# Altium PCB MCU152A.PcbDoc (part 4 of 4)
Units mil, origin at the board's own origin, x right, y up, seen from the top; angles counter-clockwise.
Board outline 2307.9 x 3007.9 mil, 4 copper layers (Top Signal, GND, PWR, Bottom Signal), stack 61.6 mil thick; 198 components, 136 nets, 740 pads, 401 vias.
Unrouted connection lines stored in the file: 147.
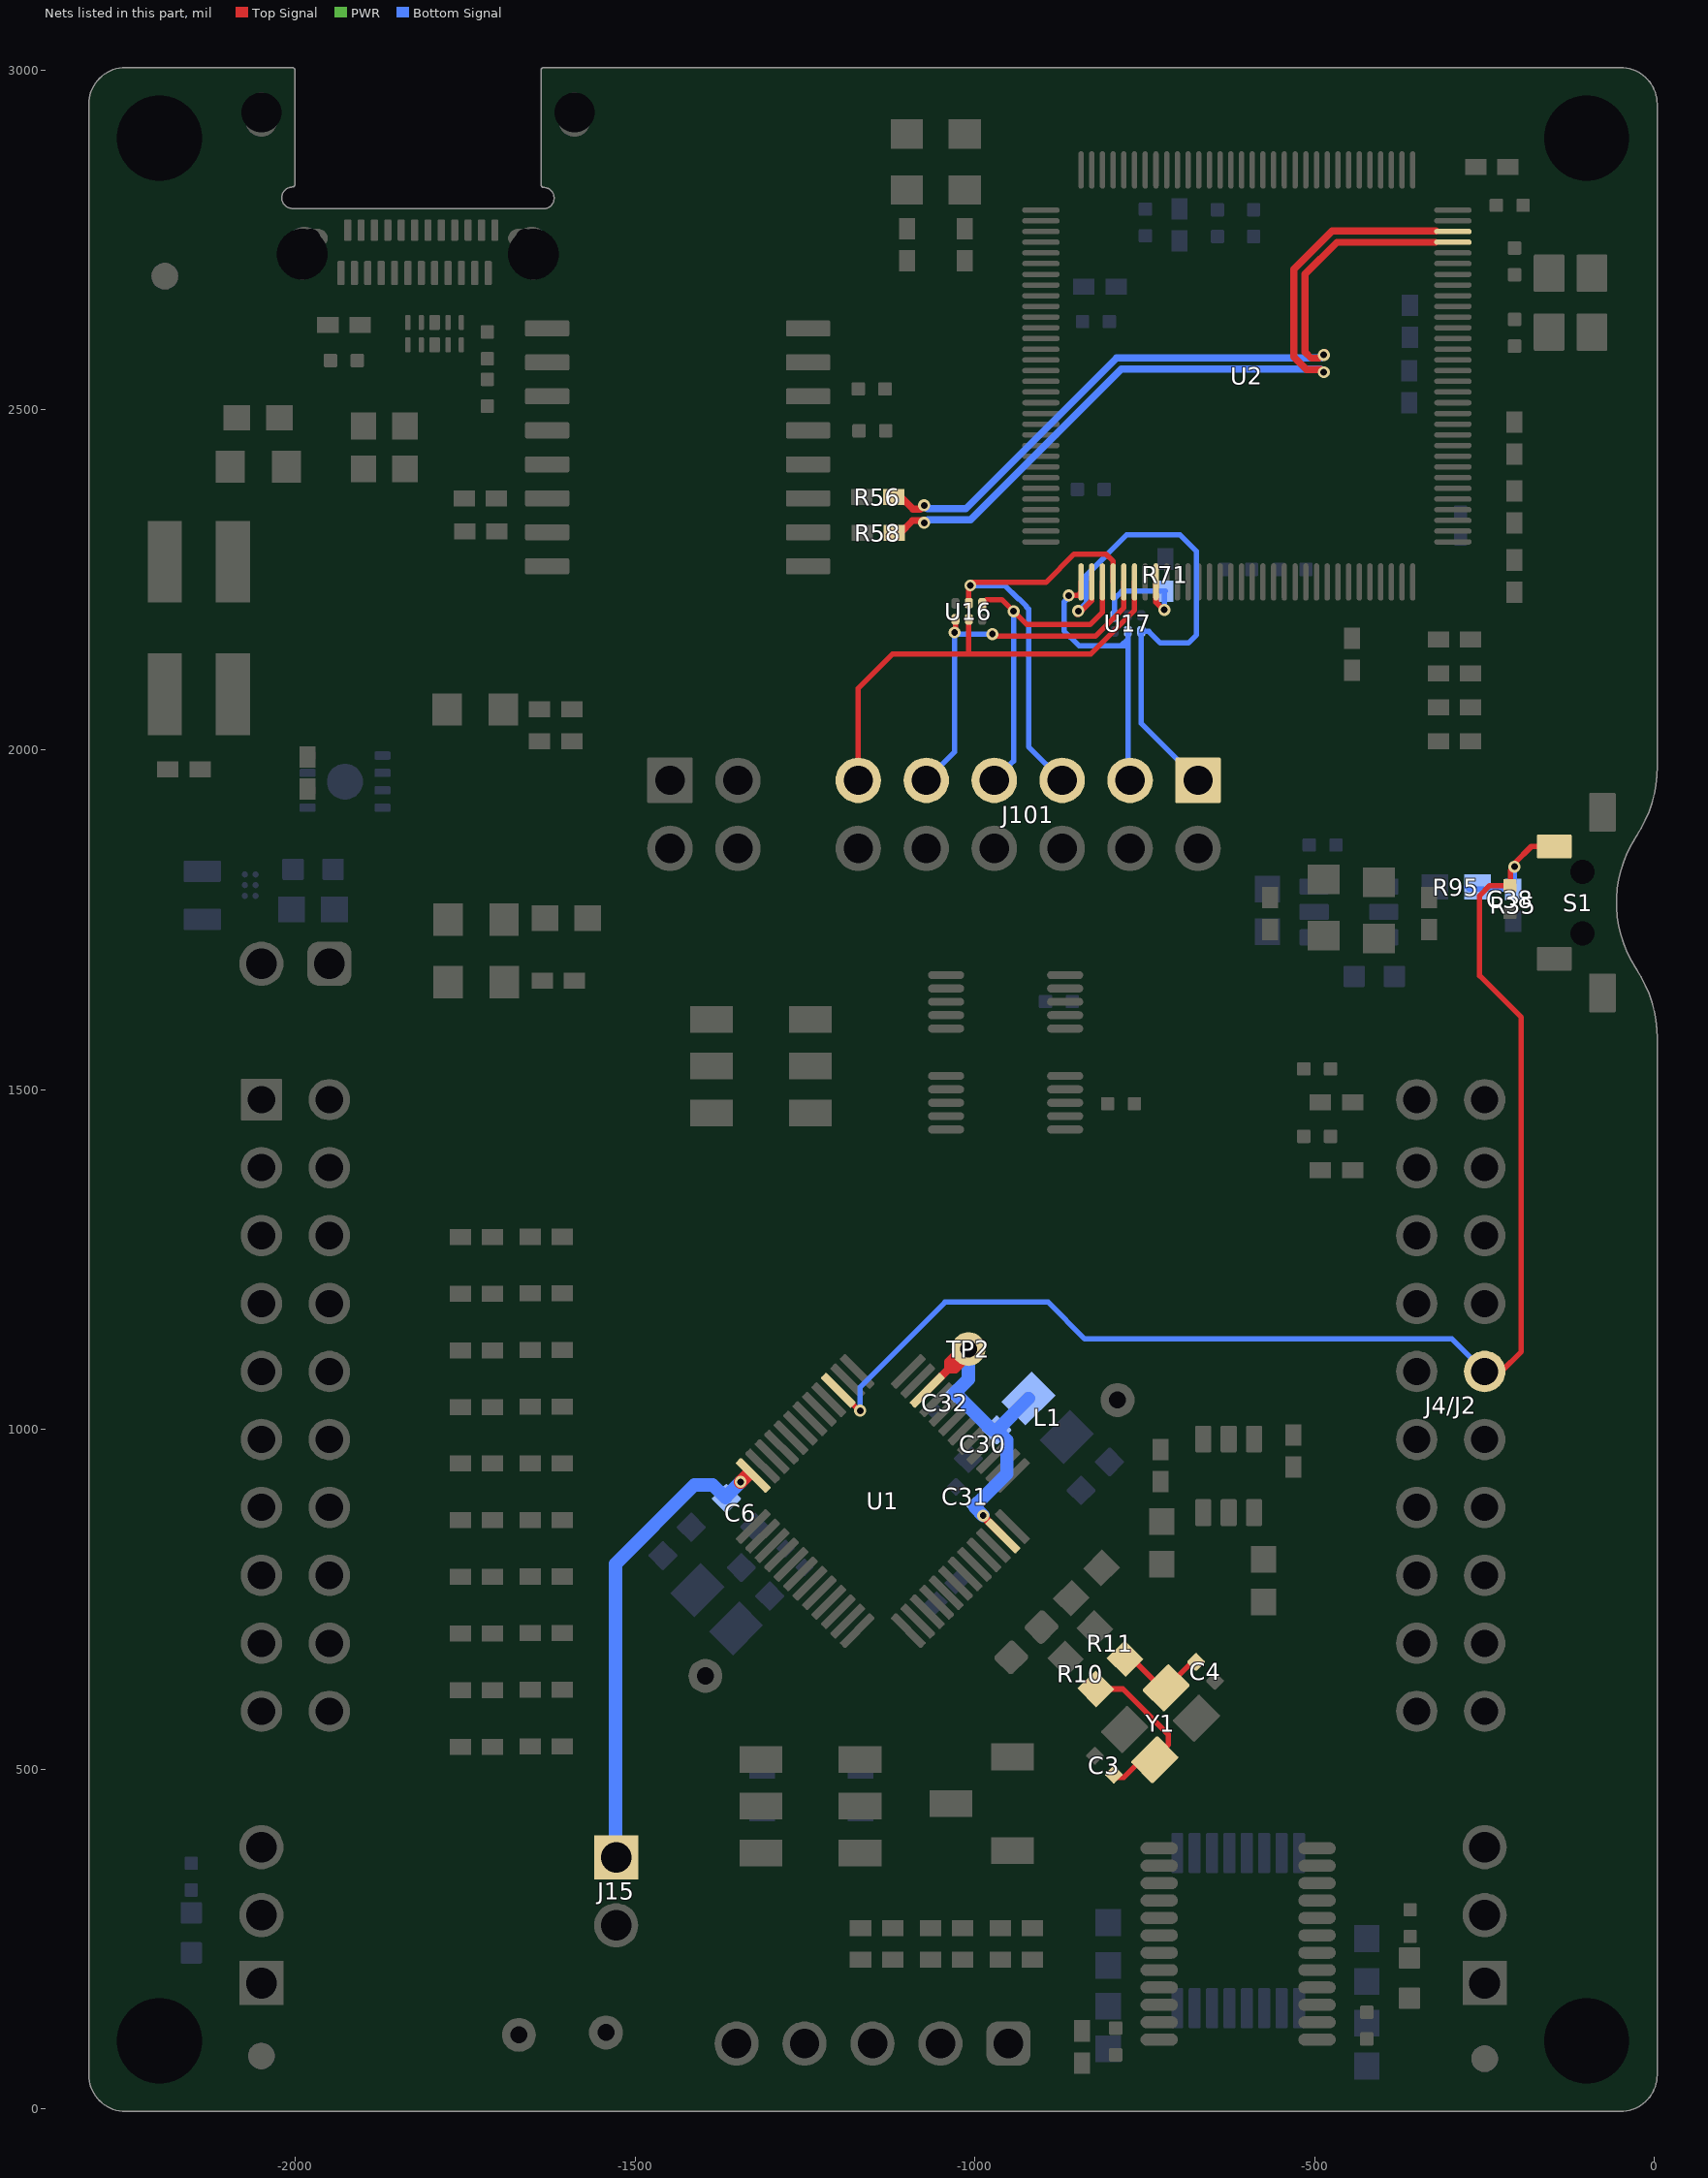
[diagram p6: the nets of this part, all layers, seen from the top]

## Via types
v1: diameter 17.72, hole 9.84, Top Signal to Bottom Signal, tented both sides, 368 vias
v2: diameter 27.56, hole 15.75, Top Signal to Bottom Signal, tented both sides, 21 vias
v3: diameter 19.68, hole 11.81, Top Signal to Bottom Signal, tented both sides, 6 vias
v4: diameter 19.68, hole 7.87, Top Signal to Bottom Signal, tented both sides, 4 vias
v5: diameter 15.75, hole 7.87, Top Signal to Bottom Signal, tented both sides, 2 vias

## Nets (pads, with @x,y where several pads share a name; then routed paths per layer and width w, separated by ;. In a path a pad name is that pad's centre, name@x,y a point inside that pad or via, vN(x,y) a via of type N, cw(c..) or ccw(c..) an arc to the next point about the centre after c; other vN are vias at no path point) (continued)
VDDIO: C30.1 C31.2 C32.2 L1.2 TP2.1 U1.35 U1.46 | length 593.5
  Top Signal w11.81: U1.46@-1070.25,1057.28 -1039.53,1088 ; TP2.1@-1016,1123 -1039.53,1099.47 -1039.53,1088 ; TP2.1@-1011,1105.66 -1028.66,1088 -1039.53,1088 ; TP2.1@-1005.53,1122 TP2.1@-1009.5,1118.03 -1039.53,1088 ; v1(-988,873) -988,872.03 U1.35@-958.89,842.92
  Bottom Signal w19.68: TP2.1@-1009.5,1118.03 -1009.5,1073.5 -1029.44,1053.56 -974.75,998.88 C30.1@-967.85,998.88 ; v1(-988,873) -1000.08,885.08 C31.2@-1000.08,887.43 -953,934.51 -953,984.03 C30.1@-967.85,998.88 ; L1.2@-921.28,1045.26 -921.47,1045.26 C30.1@-967.85,998.88
VREFHI: C6.1 J15.1 U1.12 | length 697.2
  Top Signal w19.68: v1(-1344.89,922.45) U1.12@-1334.17,933.17
  Bottom Signal w19.68: J15.1@-1529,370 -1529,802 -1413,918 -1385.89,918 -1367.16,899.27 -1367.16,900.18 v1(-1344.89,922.45)
XDS_D_N: R56.2 U2.93 | length 1103.7
  Top Signal w10.63: R56.2@-1114.25,2371.85 -1109.02,2371.85 -1091.04,2353.88 -1080.33,2353.88 v1(-1074.68,2359.53) ; v1@-485.04,2584.25 -493.03,2576.26 -505.39,2576.26 -514.17,2585.04 -514.17,2700 -467.46,2746.71 U2.93@-322.71,2746.71
  Bottom Signal w7.87: v1(-1074.68,2359.53) -1074.68,2357.29 -1073.46,2356.06 -1072.34,2357.19 v1@-1069.99,2359.53
  Bottom Signal w10.63: v1(-1074.68,2359.53) -1072.34,2357.19 -1070.13,2354.98 -1013.28,2354.98 -791.49,2576.77 -490.94,2576.77 v1(-486.61,2581.1)
XDS_D_P: R58.2 U2.94 | length 1149.7
  Top Signal w10.63: R58.2@-1114.25,2319.37 -1109.72,2319.37 -1091.75,2337.34 -1077.02,2337.34 v1@-1073.61,2333.94 ; v1@-484.25,2553.54 -490.43,2559.72 -512.24,2559.72 -530.71,2578.19 -530.71,2706.85 -474.31,2763.24 U2.94@-321.89,2763.24
  Bottom Signal w10.63: v1@-1073.61,2333.94 -1069.1,2338.45 -1006.44,2338.45 -784.65,2560.24 -491.34,2560.24 v1(-486.61,2555.51)
  other v1: -1074.68,2333.94
XDS_RESET_OUT: R71.1 U2.40 U17.1 | length 178.5
  Top Signal w7.87: U2.40@-733.66,2246.85 -733.66,2217.15 v1@-721,2204.49
  Bottom Signal w7.87: U17.1@-794.69,2196.83 -794.69,2222.31 -783.62,2233.38 R71.1@-719.82,2233.38 ; v1(-721.32,2205.89) R71.1@-721.32,2231.88
XDS_RXD: J101.3 U2.33 U17.5 | length 427.2
  Top Signal w7.87: v1(-862,2227) -848.46,2227 -843.9,2231.57 U2.33@-843.9,2246.85
  Bottom Signal w7.87: v1(-862,2227) -862,2224.11 -869,2217.11 -869,2175 -847,2153 -784.65,2153 ; U17.5@-775,2174.19 -775,2162.65 ; J101.3@-771.86,1955.19 -775,1958.33 -775,2153 ; -784.65,2153 -775,2153 ; -784.65,2153 -775,2162.65 ; -775,2153 -775,2162.65
XDS_TCK_SWDCLK: J101.7 U2.35 U16.1 | length 507.4
  Top Signal w7.87: U16.1@-989.31,2214.55 -982.87,2221 -960.52,2221 v1(-943.24,2203.72) -923.52,2184 -830.9,2184 -812.4,2202.5 U2.35@-812.4,2246.85
  Bottom Signal w7.87: J101.7@-971.67,1955 -943.24,1983.42 v1(-943.24,2203.72)
XDS_TDI: J101.11 U2.38 U16.5 | length 681.9
  Top Signal w7.87: J101.11@-1171.67,1955 -1171.67,2090.33 -1121,2141 -1009,2141 ; U16.5@-1009,2191.91 -1009,2141 ; U2.38@-765.16,2246.85 -765.16,2205.36 -829.51,2141 -1009,2141
XDS_TDO_SWO: J101.9 U2.37 U16.4 | length 558.8
  Top Signal w7.87: v1@-1028.68,2173.9 U16.4@-1028.68,2191.91 ; v1@-976,2172.51 -970.49,2167 -823,2167 -780.91,2209.09 U2.37@-780.91,2246.85
  Bottom Signal w7.87: J101.9@-1071.67,1955 -1030.07,1996.6 v1(-1030.07,2172.51) ; v1@-1027.87,2170.32 v1(-974.37,2170.32)
XDS_TMS_SWDIO: J101.5 U2.36 U16.2 | length 664.7
  Top Signal w7.87: U16.2@-1009,2215.54 -1009,2239.85 -1002.6,2246.25 -895.75,2246.25 -854,2288 -807.49,2288 -796.65,2277.17 U2.36@-796.65,2246.85
  Bottom Signal w7.87: v1(-1006.87,2241.75) -955.88,2241.75 -936.55,2222.42 -935.5,2222.42 -924.54,2211.47 -924.54,2210.41 -921,2206.87 -921,2004.33 J101.5@-871.67,1955
XDS_TXD: J101.1 U2.34 U17.4 | length 789.5
  Top Signal w7.87: v1@-850.24,2199.26 -848,2201.5 v1(-848,2204) ; v1@-848.38,2199.26 -828.15,2219.49 U2.34@-828.15,2246.85
  PWR w7.87: v1(-848,2204) v1@-845.62,2206.38
  Bottom Signal w7.87: v1(-848,2204) -836,2216 -836,2257 -777,2316 -698.09,2316 -674,2291.91 -674,2169 -686,2157 -727,2157 -744.19,2174.19 U17.4@-755.32,2174.19 -755.32,2038.65 J101.1@-671.67,1955
XRSn: C38.2 J4/J2.16 R35.1 R95.1 S1.4 U1.3 | length 2108.3
  Top Signal w7.87: U1.3@-1201.09,1057.28 -1200.28,1057.28 -1170.32,1027.32 v1(-1169,1027.32) ; J4/J2.16@-250,1085 -225.5,1085 -196.21,1114.29 -196.21,1606.21 -257.56,1667.56 -257.56,1785.03 -242.61,1799.97 C38.2@-212.72,1799.97 -212,1800.7 -212,1821.98 v1(-206,1827.98) -206,1833 -181.32,1857.68 S1.4@-147.56,1857.68
  Bottom Signal w7.87: v1(-1169,1027.32) -1169,1062 -1044,1187 -892.22,1187 -838.22,1133 -298,1133 J4/J2.16@-250,1085 ; R95.1@-276.06,1798.35 -272.61,1794.91 -216.28,1794.91 -206,1805.19 v1(-206,1827.98)
XTAL_X1: C4.1 R11.2 Y1.3 | length 138.4
  Top Signal w8: R11.2@-779.09,662.3 -768.64,662.3 -723.3,616.95 -720.78,616.95 C4.1@-677.45,660.28
XTAL_X2: C3.1 R10.2 Y1.1 | length 249.4
  Top Signal w8: R10.2@-822.1,617.81 -782.43,617.81 -715.5,550.89 -715.5,535.66 Y1.1@-737.58,513.58 ; C3.1@-792.93,488.93 -791.92,487.92 -780.87,487.92 -755.21,513.58 Y1.1@-735.35,513.58
pads on no net: FID1.1 FID2.1 FID3.1 FID4.1 FID5.1 FID6.1 H1. H2. M4.0 M5.0 M6.0 M7.0 M8.0 M9.0 M10.0 M11.0 M12.0 M13.0 MH1.1 MH2.1 MH3.1 MH4.1 S1. U1.10 U2.1 U2.2 U2.5 U2.6 U2.11 U2.12 U2.13 U2.14 U2.15 U2.18 U2.19 U2.20 U2.21 U2.22 U2.23 U2.24 U2.25 U2.27 U2.29 U2.30 U2.31 U2.32 U2.41 U2.42 U2.43 U2.44 U2.45 U2.46 U2.49 U2.50 U2.53 U2.54 U2.56 U2.57 U2.65 U2.67 U2.71 U2.72 U2.73 U2.74 U2.75 U2.76 U2.77 U2.78 U2.81 U2.82 U2.83 U2.84 U2.85 U2.86 U2.91 U2.92 U2.95 U2.97 U2.98 U2.99 U2.100 U2.102 U2.103 U2.104 U2.105 U2.106 U2.107 U2.108 U2.109 U2.110 U2.111 U2.112 U2.116 U2.117 U2.118 U2.119 U2.120 U2.121 U2.123 U2.124 U2.125 U2.126 U2.127 U2.128 U10.3 U13.3@-1795.16,2595.85 U13.8@-1795.16,2628.72 U17.2 USB1.A2 USB1.A3 USB1.A8 USB1.A10 USB1.A11 USB1.B2 USB1.B3 USB1.B8 USB1.B10 USB1.B11

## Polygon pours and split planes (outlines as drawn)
+5V0_XDS110 on PWR "PWR_+5V0_XDS110_P012" (solid, remove dead copper, pour order 12): -2294,2125.5 -2294,1920 -1416,1920 -1416,2125.5
+3V3_MCU on PWR "PWR-+3V3_MCU" (solid, remove dead copper, pour order 2): -2100.35,1748 -2100.35,537.45 -1934.91,372 -900.96,372 -751.77,237.91 -751.77,-4.93 -25,-5.4 -25,1888.19 -1400,1888.19 -1400,1779.21 -1433.42,1748
+3V3_XDS110 on PWR "PWR-+3V3_XDS110" (solid, remove dead copper, pour order 0): -1404.33,2974.51 -25,2974.51 -25,1921 -1404.52,1921 -1404.52,2190.48
+5V0_MCU on PWR "PWR-+5V0_MCU" (solid, remove dead copper, pour order 4): -1400,1888.19 -1400,1810.71 -1438.71,1772 -2103.87,1772 -2132,1743.87 -2132,426 -1986,280 -883,280 -812,209 -812,56 -851,17 -1997,17 -2266,286 -2266,1860 -2237.81,1888.19
USB_GND on PWR "Top Signal-USB_GND" (solid, remove dead copper, pour order 10): -2304.92,2223.18 -1516.66,2223.18 -1502.95,2236.89 -1502.95,3002.24 -2263.31,3002.24 -2263.31,2999.33 -2304.92,2957.72
USB_GND on GND "Top Signal-USB_GND" (solid, remove dead copper, pour order 6): -2304.92,2223.18 -1516.66,2223.18 -1502.95,2236.89 -1502.95,3002.24 -2263.31,3002.24 -2263.31,2999.33 -2304.92,2957.72
GND on GND "GND-GND" (solid, remove dead copper, pour order 8): -2300.87,2118.19 -1468.31,2118.19 -1401.97,2184.53 -1401.97,3001.65 -39.84,3001.65 0.59,2961.22 0.59,99.59 -102.95,-3.95 -2185.05,-3.95 -2300.28,111.28 -2300.28,2116.61 -2299.41,2117.48
GND on Bottom Signal "GND-GND" (solid, remove dead copper, pour order 16): -2300.87,2118.19 -1468.31,2118.19 -1401.97,2184.53 -1401.97,3001.65 -39.84,3001.65 0.59,2961.22 0.59,99.59 -102.95,-3.95 -2185.05,-3.95 -2300.28,111.28 -2300.28,2116.61 -2299.41,2117.48
USB_GND on Bottom Signal "Top Signal-USB_GND" (solid, remove dead copper, pour order 14): -2304.92,2223.18 -1516.66,2223.18 -1502.95,2236.89 -1502.95,3002.24 -2263.31,3002.24 -2263.31,2999.33 -2304.92,2957.72
USB_GND on Top Signal "Top Signal-USB_GND" (solid, remove dead copper, pour order 20): -2304.92,2223.18 -1516.66,2223.18 -1502.95,2236.89 -1502.95,3002.24 -2263.31,3002.24 -2263.31,2999.33 -2304.92,2957.72
GND on Top Signal "GND-GND" (solid, remove dead copper, pour order 18): -2300.87,2118.19 -1468.31,2118.19 -1401.97,2184.53 -1401.97,3001.65 -39.84,3001.65 0.59,2961.22 0.59,46.67 -50.02,-3.95 -2250,-3.95 -2300.28,46.32 -2300.28,2116.61 -2299.41,2117.48

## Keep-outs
Keep-Out Layer:
  lines w7.87: -2300,2950 cw(c-2250,2950) -2250,3000 ; -2300,2950 cw(c-2250,2950) -2250,3000 ; -2300,2950 -2300,50 ccw(c-2250,50) -2250,0 -50,0 ccw(c-50,50) 0,50 0,1575 ; -2250,3000 -2004.72,3000 -2250,3000 ; -50,3000 cw(c-50,2950) 0,2950 ; -50,3000 cw(c-50,2950) 0,2950 ; -50,3000 -1634.65,3000 -50,3000 ; -30,1675 cw(c-181.67,1575) 0,1575 ; -30,1675 cw(c121.67,1775) -30,1875 ; -30,1675 cw(c121.67,1775) -30,1875 ; -30,1675 cw(c-181.67,1575) 0,1575 ; -30,1875 ccw(c-181.67,1975) 0,1975 ; -30,1875 ccw(c-181.67,1975) 0,1975 ; 0,1975 0,2950 ; 0,1975 0,2950
  text ".Layer_Name" at -2242,-1581.49 h60

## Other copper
Top Signal:
  pour cut-out: -523.12,1845.41 -373.62,1845.41 -363.19,1834.98 -363.19,1657.61 -545.26,1657.61 -545.02,1661.07 -545.02,1823.51
  pour cut-out: -2046.61,2380.95 -2046.92,2381.25 -2057,2381.25 -2057,2391 -2046,2391 -2046,2381.56
  pour cut-out: -1193.58,2295.75 -1215.88,2295.75 -1216.18,2295.44 -1218.96,2298.22 -1218.96,2322.54 -1204.15,2337.34 -1186.18,2319.37 -1166.02,2319.37 -1166.02,2311.75 -1178.9,2298.87
  pour cut-out: -790.17,580.48 -764.17,572.98 -767.17,560.48 -793.21,549.42 -807.63,552.48
  pour cut-out: -902.95,2794.09 -902.95,2305.91 -843.9,2246.85 -355.71,2246.85 -296.65,2305.91 -296.65,2794.09 -355.71,2853.15 -843.9,2853.15
  pour cut-out: -1290.19,2510.98 -1290.19,2295.44 -1248.03,2295.44 -1248.03,2304.1 -1248.03,2510.98 -1289.4,2510.98
  text ".Layer_Name" at -2066.93,-1577.03 h60
Bottom Signal:
  pour cut-out: -1419.67,713.54 -1408.26,702.12 -1402.63,702.12 -1395,709.75 -1405.39,720.14 -1414,720.14 -1414,719.21
  region net NetL4_2: -2070,1803 -2070,1797.5 -2071.5,1796 -2109,1796 -2115,1802 -2115,1813 -2088,1813 -2081,1806 -2073,1806
  region net NetJ17_2: -2070,1771.28 -2091.28,1750 -2101.46,1750 -2111,1759.54 -2111,1769 -2091,1789 -2073,1789 -2070,1786
  pour cut-out: -749.41,2835.56 -709.14,2835.56 -699.17,2825.59 -720.83,2803.94 -720.83,2801.52 -727.8,2808.49
  text ".Layer_Name" at -2174.19,-1575.49 h60

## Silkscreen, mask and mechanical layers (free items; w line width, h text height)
Top Overlay:
  drawing of 5180 lines, arcs and shapes, not listed
  text "*" at -2079.74,2615.37 h25
  text "*" at -2066.98,2556.12 h25
  text "*" at -92.13,2441.63 h25
  text "+5V0" at -2274,2114.01 h51.18 r270
  text "GND" at -2044.07,2101.69 h51.18 r270
  text "XRSn" at -187,1946 h72.83
  text "➔" at -689.51,1790.7 h60 r270
  text "➔" at -753.51,1747.25 h60 r90
  text "TDI" at -1200.42,1716.77 h51.18 r45
  text "ENABLE" at -2278,1711.63 h51.18
  text "TDO" at -1102.77,1710.2 h51.18 r45
  text "TCK" at -1001.82,1708.55 h51.18 r45
  text "TMS" at -904.5,1707.9 h51.18 r45
  text "+5V0" at -1504.63,1694.68 h51.18 r45
  text "+3V3" at -1398.85,1693.47 h51.18 r45
  text "+5V0" at -2278,1672.82 h51.18
  text "RXD" at -697.59,1665.44 h51.18 r45
  text "TXD" at -796.4,1664.42 h51.18 r45
  text "BOOST" at -2277.5,1634.43 h51.18
  text "1" at -1448.85,1634.43 h51.18
  text "1" at -1202.01,1634.76 h51.18
  text "IO.0" at -573,1616.36 h51.18
  text "IO.1" at -572.31,1574.36 h51.18
  text "*" at -601.33,1517.87 h25
  text "SEL1" at -1438.71,1478 h51.18 r90
  text "SEL2" at -1160.85,1476.55 h51.18 r90
  text "*" at -599.42,1418.86 h25
  text "0" at -1443.93,1401.36 h51.18
  text "0" at -1205.98,1401.36 h51.18
  text "IO.29" at -188.5,1370.72 h51.18
  text "A4" at -2164.15,1364.75 h51.18
  text "SEL1" at -1517.38,1321.99 h51.18
  text "SEL2" at -1393.82,1321.99 h51.18
  text "IO35, IO37" at -1269.3,1314.92 h51.18
  text "*" at -1609.84,1311.71 h25
  text "IO.32" at -188.5,1275.29 h51.18
  text "IO.2" at -483,1270.57 h51.18
  text "IO.35" at -2213.83,1270 h51.18
  text "*" at -1548.2,1268.91 h25
  text "A8" at -1889.32,1265.45 h51.18
  text "0" at -1516.3,1265.48 h51.18
  text "0" at -1392.94,1264.73 h51.18
  text "UART RXD, TXD" at -1269.3,1258.74 h51.18
  text "*" at -1602.96,1228.56 h25
  text "0" at -1517.4,1214.98 h51.18
  text "1" at -1392.94,1214.87 h51.18
  text "JTAG TDI, TDO" at -1269.3,1208.74 h51.18
  text "LAUNCHXL- / F28E12X" at -1026.22,1205.45 h78.74 r0.23
  text "IO.37" at -2213.83,1170 h51.18
  text "IO.3" at -483,1170 h51.18
  text "A5" at -1888.77,1167.77 h51.18
  text "1" at -1517.38,1167.62 h51.18
  text "BoosterPack" at -1270.3,1167.87 h51.18
  text "IO.43" at -191,1168.29 h51.18
  text "X" at -1393.09,1166.62 h51.18
  text "*" at -1602.47,1144.55 h25
  text "VDDIO" at -968.19,1102.75 h51.18
  text "A12" at -1890.41,1072.83 h51.18
  text "IO.4" at -483,1071 h51.18
  text "XRSn" at -188.5,1070.29 h51.18
  text "IO.242" at -2235.5,1067 h51.18
  text "*" at -1601.88,1062.04 h25
  text "+3V3" at -758.35,1030.8 h51.18
  text "A14" at -1890.96,988.32 h51.18
  text "*" at -1600.91,978.5 h25
  text "IO.5" at -483,970 h51.18
  text "IO.16" at -188.5,970.29 h51.18
  text "A7" at -2164.15,968.53 h51.18
  text "A15" at -1890.41,951.01 h51.18
  text "*" at -1609.67,894.75 h25
  text "IO.224" at -531.44,873.67 h51.18
  text "IO.12" at -2213.83,871.1 h51.18
  text "A11" at -1891.51,870.89 h51.18
  text "IO.13" at -188.5,870.29 h51.18
  text "*" at -839.77,827.47 h25 r45
  text "*" at -1613.02,810.45 h25
  text "A16" at -1891.51,770.46 h51.18
  text "IO.24" at -2213.83,770 h51.18
  text "IO.45" at -188.5,770.29 h51.18
  text "IO.230" at -532.9,766.1 h51.18
  text "*" at -929.57,737.67 h25 r45
  text "*" at -1600.91,728.04 h25
  text "A6" at -1883.28,691.99 h51.18
  text "*" at -2239.42,673.47 h25
  text "VDDA" at -1459.02,673.45 h51.18
  text "IO.18" at -2213.83,670 h51.18
  text "IO.33" at -188.5,670.29 h51.18
  text "IO.6" at -483,667.24 h51.18
  text "A21" at -1893.16,651.93 h51.18
  text "*" at -1600.89,645.65 h25
  text "*" at -2238.92,573.37 h25
  text "IO.19" at -2213.83,570 h51.18
  text "IO.227" at -188.5,570.29 h51.18
  text "IO.7" at -483,569 h51.18
  text "A0" at -1887,568 h51.18
  text "*" at -1602.05,562.45 h25
  text "1" at -1374,550.89 h51.18
  text "BP" at -907.81,486.47 h51.18
  text "Q1" at -905.75,431.16 h51.18
  text "GPIO24" at -1367,368 h51.18 r90
  text "GPIO32" at -1093,368 h51.18 r90
  text "J12" at -906.51,364.83 h51.18
  text "VREFHI" at -1773,360 h51.18
  text "0" at -1376.63,317.56 h51.18
  text "BOOT" at -1312.2,299.93 h51.18
  text "QEP  Select" at -1100.7,299.77 h51.18
  text "EQEP1" at -1210.91,158.4 h51.18
  text "GND" at -1723.11,147.8 h51.18
  text "+5V0" at -1604.11,144.84 h51.18
  text "GND" at -1393,8 h51.18
  text "5V" at -1274.86,8 h51.18
  text "1I" at -1168,7.36 h51.18
  text "1B" at -1068,7.36 h51.18
  text "1A" at -968,7.36 h51.18
  text ".Layer_Name" at -2263,-1575.99 h60
Bottom Overlay:
  drawing of 4212 lines, arcs and shapes, not listed
  text "LAUNCHXL-F28E12X / Development Kit" at 0,2820.87 h100
  text "www.ti.com/launchpad" at 0,2025 h100
  text "40" at -421,1455 h78.74
  text "2" at -2124,1356 h78.74
  text "39" at -424,1356 h78.74
  text "19" at -111.5,1356 h78.74
  text "3" at -2124,1263.68 h78.74
  text "38" at -424,1263.68 h78.74
  text "18" at -111.5,1263.68 h78.74
  text "23" at -1811.5,1256 h78.74
  text "'.PRJ_Number'.PCB_Rev" at -861,1207 h108.27
  text "4" at -2123.5,1166.47 h78.74
  text "37" at -423.5,1166.47 h78.74
  text "17" at -111,1166.46 h78.74
  text "24" at -1811.5,1163.68 h78.74
  text "VDDIO" at -935.48,1155.28 h51.18
  text "TP2" at -1043.11,1100.11 h51.18
  text "+3V3" at -724.63,1079.34 h51.18
  text "25" at -1811,1066.46 h78.74
  text "5" at -2124,1063 h78.74
  text "36" at -424,1063 h78.74
  text "16" at -111.5,1063 h78.74
  text "TP4" at -688,1025.08 h51.18
  text "6" at -2123.5,964 h78.74
  text "35" at -423.5,964 h78.74
  text "15" at -111,964 h78.74
  text "26" at -1811.5,963 h78.74
  text "7" at -2124,865 h78.74
  text "34" at -424,865 h78.74
  text "14" at -111.5,865 h78.74
  text "27" at -1811,864 h78.74
  text "28" at -1811.5,765 h78.74
  text "8" at -2123.5,761.45 h78.74
  text "33" at -423.5,761.45 h78.74
  text "13" at -111,761.45 h78.74
  text "29" at -1811,661.45 h78.74
  text "9" at -2124.5,661 h78.74
  text "32" at -424.5,661 h78.74
  text "12" at -112,661 h78.74
  text "VDDA" at -1429.5,621.33 h51.18
  text "TP3" at -1361.04,565.27 h51.18
  text "30" at -1812,561 h78.74
  text "10" at -2124.5,557.97 h78.74
  text "31" at -424.5,557.97 h78.74
  text "11" at -112,557.97 h78.74
  text "*" at -857.22,320.39 h25
  text "*" at -458.07,299.59 h25
  text "Not FCC approved for resale" at -902.5,199.12 h60
  text "GND" at -1626.56,150 h51.18
  text "+5V0" at -1480,148 h51.18
  text "TP5" at -1506,41 h51.18
  text "TP6" at -1631.18,40 h51.18
  text "5V" at -1229.2,9.57 h51.18
  text "1I" at -1134,9.46 h51.18
  text "1B" at -1025.28,9.46 h51.18
  text "1A" at -923.64,9.46 h51.18
  text "GND" at -1310,9 h51.18
  text ".Layer_Name" at -2263,-1575.99 h60
Top Paste:
  text ".Layer_Name" at -2263,-1580.99 h60
Bottom Paste:
  text ".Layer_Name" at -2263,-1580.99 h60
Top Solder:
  text ".Layer_Name" at -2258,-1575.99 h60
  text ".Layer_Name" at -2258,-1575.99 h60
Bottom Solder:
  text ".Layer_Name" at -2258,-1575.99 h60
Drill Guide:
  text ".Layer_Name" at -2258,-1575.99 h60
M1 Board Outline:
  lines w7.87: -2005.64,2792.67 cw(c-2004.37,2812.32) -2004.72,2832 -2004.72,3000 ; -2004.72,2792.13 -1634.65,2792.13 ; -1633.73,2792.17 ccw(c-1635,2811.82) -1634.65,2831.5 -1634.65,3000 ; -2300,2950 cw(c-2250,2950) -2250,3000 ; -2300,2950 cw(c-2250,2950) -2250,3000 ; -2300,2950 -2300,50 ccw(c-2250,50) -2250,0 -50,0 ccw(c-50,50) 0,50 0,1575 ; -2250,3000 -2004.72,3000 ; -2250,3000 -2004.72,3000 ; -1634.65,3000 -50,3000 ; -1634.65,3000 -50,3000 ; -50,3000 cw(c-50,2950) 0,2950 ; -50,3000 cw(c-50,2950) 0,2950 ; -30,1675 cw(c-181.67,1575) 0,1575 ; -30,1675 cw(c121.67,1775) -30,1875 ; -30,1675 cw(c121.67,1775) -30,1875 ; -30,1675 cw(c-181.67,1575) 0,1575 ; -30,1875 ccw(c-181.67,1975) 0,1975 ; -30,1875 ccw(c-181.67,1975) 0,1975 ; 0,1975 0,2950 ; 0,1975 0,2950
  text ".Layer_Name" at -2198,-1575.49 h60
M2 Board Dimensions:
  text ".Layer_Name" at -2172.88,-1577.91 h60
M3 3D STEP Top:
  text ".Layer_Name" at -2128,-1578.49 h60
M4 3D STEP Bottom:
  text ".Layer_Name" at -2178,-1575.49 h60
M5 Assembly Top:
  lines w10: -3132.5,-1652.67 3467.5,-1652.67 ; -3132.5,-1449.33 3469.5,-1449.33 ; -3132.5,-1246 -3132.5,-1856 872.5,-1856 3469.5,-1856 3469.5,-1246 -3132,-1246 -3132,-1856 -1556.5,-1856 ; -667.5,-1856 -667.5,-1246 ; 599.5,-1449.33 599.5,-1246 ; 1439.5,-1449.33 1439.5,-1246 ; 2061.5,-1862.5 2061.5,-1659.67
  text "Place a click-in Standoff (MAE-10, KangYang) in hole MH1/MH2" at -1798,6568 h40
  text "COMPONENTS MARKED 'DNP' SHOULD NOT BE POPULATED." at -2720.72,-800.5 h60
  text "ASSEMBLY VARIANT:" at -2721.22,-916 h60
  text ".VariantName" at -1685.22,-916 h60
  text "PCB VIEWED FROM TOP SIDE" at -3069,-1378.17 h60
  text "BOARD #:" at -592.5,-1378.17 h60
  text ".PRJ_Number" at -47,-1378.17 h60
  text "REV:" at 797.5,-1378.17 h60
  text ".PCB_Rev" at 1089,-1378.17 h60
  text "SVN REV:" at 1635.5,-1378.17 h60
  text ".VersionControl_RevNumber" at 2141.5,-1378.17 h60
  text "TID #:" at -592.5,-1581.5 h60
  text ".TID" at -47,-1581.5 h60
  text ".Layer_Name" at -2260.5,-1582.5 h60
  text "PLOT NAME =" at -3069,-1786.84 h60
  text ".plot_File_Name" at -2263.5,-1786.84 h60
  text "GENERATED    :" at -590.5,-1786.84 h60
  text ".Print_Date" at 279,-1786.84 h60
  text ".Print_Time" at 1008,-1786.84 h60
  text "TEXAS INSTRUMENTS" at 2272.5,-1786.84 h60
M6 Assembly Bottom:
  lines w10: -3130,-1449.33 3472,-1449.33 ; -3128,-1652.67 3472,-1652.67 ; -1722,-1862.5 -1722,-1659.67 ; -1100,-1449.33 -1100,-1246 ; -260,-1449.33 -260,-1246 ; 1007,-1856 1007,-1246 ; 1896,-1856 3471.5,-1856 3471.5,-1246 -3130,-1246 -3130,-1856 -533,-1856 3472,-1856 3472,-1246
  text "COMPONENTS MARKED 'DNP' SHOULD NOT BE POPULATED." at 3264.5,-1040 h60
  text ".VariantName" at 2220.5,-1156 h60
  text "ASSEMBLY VARIANT:" at 3259.5,-1156 h60
  text ".VersionControl_RevNumber" at -1802,-1378.17 h60
  text "SVN REV:" at -1296,-1378.17 h60
  text ".PCB_Rev" at -749.5,-1378.17 h60
  text "REV:" at -458,-1378.17 h60
  text ".PRJ_Number" at 386.5,-1378.17 h60
  text "BOARD #:" at 932,-1378.17 h60
  text "PCB VIEWED FROM BOTTOM SIDE" at 3408.5,-1378.17 h60
  text ".TID" at 386.5,-1581.5 h60
  text "TID #:" at 932,-1581.5 h60
  text ".Layer_Name" at -2257.5,-1582 h60
  text "TEXAS INSTRUMENTS" at -1933,-1786.84 h60
  text ".Print_Time" at -668.5,-1786.84 h60
  text ".Print_Date" at 60.5,-1786.84 h60
  text "GENERATED    :" at 930,-1786.84 h60
  text ".plot_File_Name" at 2603,-1786.84 h60
  text "PLOT NAME =" at 3408.5,-1786.84 h60
M7 LPKF Text Top:
  text ".Layer_Name" at -2258.5,-1575.8 h60
M8 LPKF Text Bottom:
  text ".Layer_Name" at -2256.87,-1578.03 h60
M9 Title Sheet:
  drawing of 57 lines, arcs and shapes, not listed
  text "1" at -2098.66,7317.96 h70
  text "2" at 397,7317.96 h70
  text "3" at 2886.34,7317.96 h70
  text "4" at 5393.01,7317.96 h70
  text "5" at 7892,7317.96 h70
  text "6" at 10397,7317.96 h70
  text "A" at -3255,6174.96 h70
  text "A" at 11545,6174.96 h70
  text "B" at -3255,3794.96 h70
  text "B" at 11545,3794.96 h70
  text "C" at -3255,1419.96 h70
  text "C" at 11545,1419.96 h70
  text "PROJECT TITLE:" at 8505,-441.04 h45
  text ".PRJ_Title" at 8555,-574.37 h70
  text "DESIGNED FOR:" at 8505,-742.04 h45
  text ".PRJ_Customer" at 8555,-882.04 h70
  text "D" at -3255,-950.04 h70
  text "D" at 11545,-950.04 h70
  text "FILE NAME:" at 8505,-1042.04 h45
  text ".PCB_File_Name_No_Path" at 8555,-1162.04 h70
  text "Texas Instruments (TI) and/or its licensors do not warrant the accuracy or completeness of this specification" at 3535.5,-1323.88 h45
  text "ENGINEER:" at 8505,-1332.04 h45
  text "LAYOUT BY:" at 10010,-1332.04 h45
  text "or any information contained therein. TI and/or its licensors do not warrant that this design will meet" at 3490.51,-1436.55 h45
  text ".PRJ_Engineer" at 8555,-1487.03 h70
  text ".PCB_Layout" at 10060.5,-1487.03 h70
  text "the specifications, will be suitable for your application or fit for any particular purpose, or will operate in" at 3490.51,-1549.21 h45
  text ".Layer_Name" at -2261.5,-1577.04 h60
  text "ALTIUM DESIGNER VERSION:" at 10010,-1642.04 h45
  text "an implementation. TI and/or its licensors do not warrant that the design is production worthy. You should" at 3490.51,-1661.88 h45
  text "completely validate and test your design implementation to confirm the system functionality for your application." at 3535.5,-1774.54 h45
  text ".print_Scale" at 8555,-1775.37 h70
  text ".Application_BuildNumber" at 10060.5,-1775.37 h70
  text "1" at -2098.66,-1982.04 h70
  text "2" at 397,-1982.04 h70
  text "3" at 2886.34,-1982.04 h70
  text "4" at 5393.01,-1982.04 h70
  text "5" at 7892,-1982.04 h70
  text "6" at 10397,-1982.04 h70
M10 Fab Notes:
  drawing of 189 lines, arcs and shapes, not listed
  text "DESIGN INFORMATION" at 9549.02,5648.17 h60
  text "MIN. TRACK WIDTH:" at 8904.46,5516.05 h60
  text "5" at 10000.7,5516.05 h60
  text "MIL" at 10155.46,5516.05 h60
  text "0.15" at 9900,5400 h60
  text "MIN. CLEARANCE:" at 8904.46,5391.92 h60
  text "mm" at 10155.46,5391.92 h60
  text "MIN. VIA PAD SIZE:" at 8904.46,5267.8 h60
  text "0.45" at 9900,5267.8 h60
  text "mm" at 10155.46,5267.8 h60
  text "0.05mm (2MIL)" at 9599.46,5137.9 h60
  text "MINIMUM ANNULAR RING" at 8575.23,5129.67 h60
  text "EXTERNAL" at 10307.46,5129.67 h60
  text "PER" at 8775.23,5019.55 h60
  text "IPC-D-275 CLASS 2 LEVEL C" at 8995.23,5019.54 h60
  text "MIL, HOLES" at 10483.46,4919.07 h60
  text "+/-" at 10091,4910.48 h60
  text "+/-" at 10945,4910.48 h60
  text "5" at 10351.2,4909.42 h60
  text "3" at 11184.2,4909.42 h60
  text "REGISTRATION TOLERANCES:" at 8575.23,4909.42 h60
  text "METAL" at 9775,4909.42 h60
  text "MIL" at 11300.46,4909.42 h60
  text "HOLE SIZE TOLERANCE (UNLESS OTHERWISE SPECIFIED):" at 8575.23,4811.1 h60
  text "+/-" at 10945,4808.23 h60
  text "5" at 11184.2,4807.17 h60
  text "MIL" at 11300.46,4807.17 h60
  text "MATERIAL:" at 8500.46,4669.52 h60
  text "FR-4 High Tg" at 9486.9,4541 h60
  text "X" at 9342.46,4533.01 h60
  text "FR-408" at 8921.46,4528.49 h60
  text "OTHER" at 10409.46,4528.49 h60
  text "62 MIL (1.6mm) +/-10%" at 9241.56,4385.46 h60
  text "X" at 9121.46,4383.01 h60
  text "THICKNESS:" at 8575.23,4377.24 h60
  text "OTHER" at 10526.46,4377.24 h60
  text "TOLERANCE:" at 8575.23,4238.92 h60
  text "ANSI IPC-6012 TYPE 3 CLASS 2" at 9601.48,4238.92 h60
  text "IPC-A600" at 10287,4112 h72.83
  text "OTHER +/-" at 9601.46,4094.73 h60
  text "X" at 9432,4092 h60
  text "BOW & TWIST:" at 8575.23,3949.54 h60
  text "ANSI IPC-6012 TYPE 3 CLASS 2" at 9601.48,3949.54 h60
  text "X" at 9422,3827 h60
  text "IPC-A600" at 10287,3807 h72.83
  text "OTHER +/-" at 9601.46,3802.85 h60
  text "DRILLING:" at 8500.46,3672.23 h60
  text "NC_DRILL FILES" at 10261.46,3567.04 h60
  text "REFERENCE:" at 8575.23,3563.1 h60
  text "X" at 9232.46,3563.01 h60
  text "AS SHOWN" at 9410.46,3563.1 h60
  text "X" at 10133.46,3563.1 h60
  text "OTHER" at 10559.46,3420.85 h60
  text "PTH COPPER THICKNESS:" at 8574.91,3417.32 h60
  text "X" at 9714.14,3417.32 h60
  text "20-30 um" at 9842.14,3417.32 h60
  text "BOARD FINISH:" at 8500.46,3269.73 h60
  text "SILKSCREEN:" at 8655.68,3159.6 h60
  text "X" at 9613.46,3159.6 h60
  text "TOP" at 9730.46,3159.6 h60
  text "X" at 10123.46,3159.6 h60
  text "BOTTOM" at 10241.46,3159.6 h60
  text "SILKSCREEN COLOR:" at 8655.68,3004.41 h60
  text "X" at 9612.46,3004.41 h60
  text "WHITE" at 9730.46,3004.41 h60
  text "OTHER" at 10241.46,3004.41 h60
  text "RED" at 10879,2871 h80
  text "GREEN" at 9861.46,2860.96 h60
  text "OTHER" at 10479.46,2860.96 h60
  text "X" at 10333,2857 h60
  text "SOLDER RESIST COLOR:" at 8655.68,2854.1 h60
  text "MATTE" at 9861.46,2706.71 h60
  text "SEMI-GLOSS" at 10479,2706.07 h60
  text "IMMERSION GOLD (ENIG)" at 9561.46,2533.94 h60
  text "ENEPIG" at 10899,2526.72 h60
  text "SURFACE FINISH:" at 8500.46,2525.72 h60
  text "IMM. TIN/SILVER OR EQUIV" at 8830,2388.4 h60
  text "X" at 8682,2387 h60
  text "OTHER" at 10261.46,2384.47 h60
  text "ARRAY/PANEL:" at 8500.46,2229.09 h60
  text "CUT AND TRIM PER M1 BOARD OUTLINE" at 9561.46,2220.87 h60
  text "X" at 9383,2219 h60
  text "N.C. ROUTE" at 9561.46,2084.9 h60
  text "V. SCORE" at 10427.46,2084.9 h60
  text "CERTIFICATION:" at 8500.46,1955.77 h60
  text "MATERIALS AND WORKMANSHIP FOR ALL PCBS" at 9225.46,1955.77 h60
  text "TO MEET OR EXCEED THE REQUIREMENTS OF:" at 9225.46,1861.71 h60
  text "X" at 10639.97,1735.39 h60
  text "X" at 8862.97,1733.08 h60
  text "ANSI IPC-A-600F CLASS ->" at 8990.96,1733.08 h60
  text "2" at 10748.96,1733.08 h60
  text "1" at 10433.96,1731.58 h60
  text "3" at 11102.96,1731.58 h60
  text "X" at 9674.97,1585.39 h60
  text "RoHS" at 9802.96,1585.39 h60
  text "OTHER" at 10447.36,1585.39 h60
  text "PER ORDER" at 10844.42,1585.39 h60
  text "ALL BOARDS MUST MEET OR EXCEED UL94-V0 REQUIREMENTS." at 8528,1431.57 h60
  text "PCB MUST BEAR THE UL94V-0 UL REGISTERED MATERIAL ID NUMBER" at 8528,1315.5 h60
  text "ADDITIONAL REQUIREMENTS:" at 8500.46,1146.08 h60
  text "MICROSECTION:" at 8575.23,1038.95 h60
  text "YES" at 9480.96,1038.95 h60
  text "X" at 9759,897 h60
  text "REQUIRED" at 10342.46,894.62 h60
  text "BARE BOARD ELEC. TEST:" at 8575.23,891.76 h60
  text "NONE" at 9880.96,891.76 h60
  text "PER ORDER" at 10934.46,891.76 h60
  text "XX MIL VIAS REQUIRE NON-CONDUCTIVE FILL AND PLANARIZE" at 8743.38,686.82 h59
  text "XX MIL VIAS REQUIRE CONDUCTIVE FILL AND PLANARIZE" at 8751.38,582.84 h60
  text "OUTER XX MIL VIAS REQUIRE 50 OHM SINGLE-ENDED IMPEDANCE" at 8750.39,419.46 h58
  text "LAYER 2 & 3 (INNER LAYERS) XX MIL WIDE, XX MIL SPACE / TRACES REQUIRE 100 OHM DIFFERENTIAL IMPEDANCE" at 8742.39,183.74 h60
  text ".Layer_Name" at -2204,-1578.49 h60
M11 Gerber Information:
  lines w10: -3131,-1649.17 3469,-1649.17 ; -3131,-1445.83 3471,-1445.83 ; -3131,-1242.5 -3131,-1852.5 874,-1852.5 3471,-1852.5 3471,-1242.5 -3130.5,-1242.5 -3130.5,-1852.5 -1555,-1852.5 ; -666,-1852.5 -666,-1242.5 ; 601,-1445.83 601,-1242.5 ; 1441,-1445.83 1441,-1242.5 ; 2063,-1859 2063,-1656.17
  text "ALL ARTWORK VIEWED FROM TOP SIDE" at -3067.5,-1374.67 h60
  text "BOARD #:" at -591,-1374.67 h60
  text ".PRJ_Number" at -45.5,-1374.67 h60
  text "REV:" at 799,-1374.67 h60
  text ".PCB_Rev" at 1090.5,-1374.67 h60
  text "SVN REV:" at 1637,-1374.67 h60
  text ".VersionControl_RevNumber" at 2143,-1374.67 h60
  text "LAYER NAME =" at -3067.5,-1577.49 h60
  text "TID #:" at -591,-1578 h60
  text ".TID" at -45.5,-1578 h60
  text ".Layer_Name" at -2259,-1579 h60
  text "PLOT NAME =" at -3067.5,-1783.34 h60
  text ".plot_File_Name" at -2262,-1783.34 h60
  text "GENERATED    :" at -589,-1783.34 h60
  text ".Print_Date" at 280.5,-1783.34 h60
  text ".Print_Time" at 1009.5,-1783.34 h60
  text "TEXAS INSTRUMENTS" at 2274,-1783.34 h60
M12 Stackup:
  drawing of 550 lines, arcs and shapes, not listed
  text "Use Standard 4 Layer Stackup" at 2869,3846 h250
  text "Layer" at 1023.2,3551 h60
  text "Name" at 1433.11,3551 h60
  text "Material" at 2362.85,3551 h60
  text "Thickness" at 3222.62,3551 h60
  text "Constant" at 3872.46,3551 h60
  text "Board Layer Stack" at 4442.32,3551 h60
  text "Board Layer Stack" at 5562,3551 h60
  text "Board Layer Stack" at 6681.68,3551 h60
  text "Top Overlay" at 1433.11,3431 h60
  text "Top Solder" at 1433.11,3311 h60
  text "Solder Resist" at 2362.85,3311 h60
  text "0.40mil" at 3222.62,3311 h60
  text "3.5" at 3872.46,3311 h60
  text "1" at 1023.2,3191 h60
  text "Top Signal" at 1433.11,3191 h60
  text "1.40mil" at 3222.62,3191 h60
  text "Dielectric 1" at 1433.11,3071 h60
  text "FR-4" at 2362.85,3071 h60
  text "8.00mil" at 3222.62,3071 h60
  text "4.2" at 3872.46,3071 h60
  text "2" at 1023.2,2951 h60
  text "GND" at 1433.11,2951 h60
  text "1.40mil" at 3222.62,2951 h60
  text "Dielectric 2" at 1433.11,2831 h60
  text "FR-4" at 2362.85,2831 h60
  text "40.00mil" at 3222.62,2831 h60
  text "4.2" at 3872.46,2831 h60
  text "3" at 1023.2,2711 h60
  text "PWR" at 1433.11,2711 h60
  text "1.40mil" at 3222.62,2711 h60
  text "Dielectric 3" at 1433.11,2591 h60
  text "FR-4" at 2362.85,2591 h60
  text "8.00mil" at 3222.62,2591 h60
  text "4.2" at 3872.46,2591 h60
  text "4" at 1023.2,2471 h60
  text "Bottom Signal" at 1433.11,2471 h60
  text "1.40mil" at 3222.62,2471 h60
  text "Bottom Solder" at 1433.11,2351 h60
  text "Solder Resist" at 2362.85,2351 h60
  text "0.40mil" at 3222.62,2351 h60
  text "3.5" at 3872.46,2351 h60
  text "Bottom Overlay" at 1433.11,2231 h60
  text ".Layer_Name" at -2253,-1590.99 h60
M13 Component Bodies Top:
  text ".Layer_Name" at -2276,-1579.49 h60
M14 Component Bodies Bottom:
  text ".Layer_Name" at -2273,-1584.49 h60
M15 Courtyards Top:
  text ".Layer_Name" at -2257,-1578.49 h60
M16 Courtyards Bottom:
  text ".Layer_Name" at -2263,-1580.99 h60
Drill Drawing:
  drawing of 152 lines, arcs and shapes, not listed
  text "Symbol" at 2772.55,1663.76 h72
  text "Count" at 3073.12,1663.76 h72
  text "Finished Hole Size" at 3375.76,1663.76 h72
  text "Plated" at 4012.32,1663.76 h72
  text "Hole Type" at 4271.47,1663.76 h72
  text "Drill Layer Pair" at 4646.62,1663.76 h72
  text "Hole Tolerance (+)" at 5402.31,1663.76 h72
  text "6" at 3073.12,1539.44 h60
  text "7.87mil (0.200mm)" at 3375.76,1539.44 h60
  text "PTH" at 4012.32,1539.44 h60
  text "Round" at 4271.47,1539.44 h60
  text "Top Signal - Bottom Signal" at 4646.62,1539.44 h60
  text "368" at 3073.12,1415.12 h60
  text "9.84mil (0.250mm)" at 3375.76,1415.12 h60
  text "PTH" at 4012.32,1415.12 h60
  text "Round" at 4271.47,1415.12 h60
  text "Top Signal - Bottom Signal" at 4646.62,1415.12 h60
  text "6" at 3073.12,1290.8 h60
  text "11.81mil (0.300mm)" at 3375.76,1290.8 h60
  text "PTH" at 4012.32,1290.8 h60
  text "Round" at 4271.47,1290.8 h60
  text "Top Signal - Bottom Signal" at 4646.62,1290.8 h60
  text "21" at 3073.12,1166.48 h60
  text "15.75mil (0.400mm)" at 3375.76,1166.48 h60
  text "PTH" at 4012.32,1166.48 h60
  text "Round" at 4271.47,1166.48 h60
  text "Top Signal - Bottom Signal" at 4646.62,1166.48 h60
  text "5" at 3073.12,1042.16 h60
  text "25.00mil (0.635mm)" at 3375.76,1042.16 h60
  text "PTH" at 4012.32,1042.16 h60
  text "Round" at 4271.47,1042.16 h60
  text "Top Signal - Bottom Signal" at 4646.62,1042.16 h60
  text "2" at 3073.12,917.84 h60
  text "27.56mil (0.700mm)" at 3375.76,917.84 h60
  text "PTH" at 4012.32,917.84 h60
  text "Slot" at 4271.47,917.84 h60
  text "Top Signal - Bottom Signal" at 4646.62,917.84 h60
  text "2" at 3073.12,793.52 h60
  text "35.43mil (0.900mm)" at 3375.76,793.52 h60
  text "NPTH" at 4012.32,793.52 h60
  text "Round" at 4271.47,793.52 h60
  text "Top Signal - Bottom Signal" at 4646.62,793.52 h60
  text "40" at 3073.12,669.2 h60
  text "40.16mil (1.020mm)" at 3375.76,669.2 h60
  text "PTH" at 4012.32,669.2 h60
  text "Round" at 4271.47,669.2 h60
  text "Top Signal - Bottom Signal" at 4646.62,669.2 h60
  text "5" at 3073.12,544.88 h60
  text "43.31mil (1.100mm)" at 3375.76,544.88 h60
  text "PTH" at 4012.32,544.88 h60
  text "Round" at 4271.47,544.88 h60
  text "Top Signal - Bottom Signal" at 4646.62,544.88 h60
  text "1.97mil (0.050mm)" at 5402.31,544.88 h60
  text "16" at 3073.12,420.56 h60
  text "43.31mil (1.100mm)" at 3375.76,420.56 h60
  text "PTH" at 4012.32,420.56 h60
  text "Round" at 4271.47,420.56 h60
  text "Top Signal - Bottom Signal" at 4646.62,420.56 h60
  text "10" at 3073.12,296.24 h60
  text "45.28mil (1.150mm)" at 3375.76,296.24 h60
  text "PTH" at 4012.32,296.24 h60
  text "Round" at 4271.47,296.24 h60
  text "Top Signal - Bottom Signal" at 4646.62,296.24 h60
  text "2" at 3073.12,171.92 h60
  text "59.06mil (1.500mm)" at 3375.76,171.92 h60
  text "PTH" at 4012.32,171.92 h60
  text "Slot" at 4271.47,171.92 h60
  text "Top Signal - Bottom Signal" at 4646.62,171.92 h60
  text "2" at 3073.12,47.6 h60
  text "74.80mil (1.900mm)" at 3375.76,47.6 h60
  text "PTH" at 4012.32,47.6 h60
  text "Slot" at 4271.47,47.6 h60
  text "Top Signal - Bottom Signal" at 4646.62,47.6 h60
  text "4" at 3073.12,-76.72 h60
  text "125.00mil (3.175mm)" at 3375.76,-76.72 h60
  text "NPTH" at 4012.32,-76.72 h60
  text "Round" at 4271.47,-76.72 h60
  text "Top Signal - Bottom Signal" at 4646.62,-76.72 h60
  text "489 Total" at 3073.12,-201.04 h60
  text "Slot definitions :" at 2772.55,-288.07 h60
  text "Routed Path Length" at 3223.27,-288.07 h60
  text "= Calculated from tool start centre position to tool end centre position." at 3763.01,-288.07 h60
  text "Hole Length" at 3223.27,-337.8 h60
  text "= Routed Path Length + Tool Size = Slot length as defined in the PCB layout" at 3563.21,-337.8 h60
  text ".Layer_Name" at -2245,-1582.49 h60
Mechanical 17:
  text ".Layer_Name" at -2268,-1570.99 h60
Mechanical 18:
  text ".Layer_Name" at -2258,-1580.99 h60
Mechanical 19:
  text ".Layer_Name" at -2263,-1580.99 h60

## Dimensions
-2300,0 to 0,0 on M2 Board Dimensions
-2300,3000 to -2300,0 on M2 Board Dimensions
